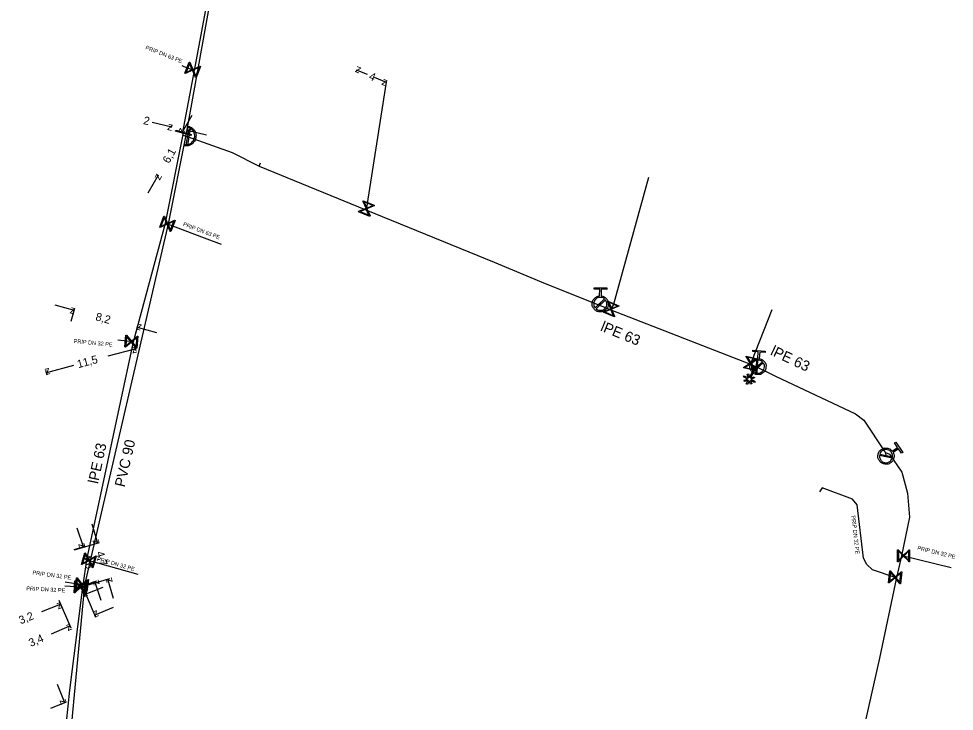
# Model space of a CAD drawing. Extents: x -641905 to -641246, y -1111750 to -1110210.
# Drawn here: x -641704.4 to -641587.5, y -1110847.5 to -1110760.9 of the extents above; entities that cross this region are included whole.
import ezdxf

# ---------------------------------------------------------------- set-up
doc = ezdxf.new("R2010")
doc.units = 0
for name, color, linetype in [('Default', 7, 'Continuous'), ('VP Hydrant', 7, 'Continuous'), ('VP Kótování', 7, 'Continuous'), ('VP Nepropojené křížení', 7, 'Continuous'), ('VP Popis přípojky', 7, 'Continuous'), ('VP Přípojka', 7, 'Continuous'), ('VP Změna materiálu', 7, 'Continuous'), ('VP Řad', 7, 'Continuous'), ('VP Řad - popis', 7, 'Continuous'), ('VP Šoupě', 7, 'Continuous')]:
    doc.layers.add(name, color=color, linetype=linetype)

msp = doc.modelspace()

# ---------------------------------------------------------------- linework, layer by layer
at = {"layer": 'Default'}
for points in [[(-641683.32, -1110774.29), (-641683, -1110774.35), (-641682.73, -1110774.57), (-641682.47, -1110774.79), (-641682.36, -1110775.11), (-641682.26, -1110775.44), (-641682.32, -1110775.75), (-641682.38, -1110776.06), (-641682.59, -1110776.32), (-641682.8, -1110776.59), (-641683.13, -1110776.7), (-641683.45, -1110776.81), (-641683.78, -1110776.75)], [(-641683.75, -1110776.6), (-641683.46, -1110776.65), (-641683.18, -1110776.55), (-641682.89, -1110776.45), (-641682.71, -1110776.22), (-641682.52, -1110775.99), (-641682.47, -1110775.72), (-641682.42, -1110775.45), (-641682.51, -1110775.16), (-641682.6, -1110774.88), (-641682.83, -1110774.69), (-641683.07, -1110774.5), (-641683.35, -1110774.44)], [(-641631.66, -1110795.52), (-641631.3, -1110795.56), (-641631.04, -1110795.82), (-641630.76, -1110796.12), (-641630.76, -1110796.53), (-641630.76, -1110796.95), (-641631.06, -1110797.23), (-641631.36, -1110797.52), (-641631.77, -1110797.52), (-641632.18, -1110797.52), (-641632.47, -1110797.22), (-641632.76, -1110796.93), (-641632.76, -1110796.51), (-641632.76, -1110796.1), (-641632.46, -1110795.81), (-641632.2, -1110795.55), (-641631.84, -1110795.52)], [(-641631.25, -1110795.89), (-641631.46, -1110795.71), (-641631.75, -1110795.71), (-641632.09, -1110795.7), (-641632.33, -1110795.94), (-641632.57, -1110796.17), (-641632.57, -1110796.51), (-641632.58, -1110796.8), (-641632.4, -1110797.02)], [(-641632.27, -1110797.15), (-641632.06, -1110797.33), (-641631.77, -1110797.33), (-641631.43, -1110797.33), (-641631.19, -1110797.1), (-641630.95, -1110796.86), (-641630.95, -1110796.53), (-641630.95, -1110796.24), (-641631.12, -1110796.02)], [(-641611.89, -1110803.37), (-641611.53, -1110803.43), (-641611.29, -1110803.7), (-641611.02, -1110804.02), (-641611.05, -1110804.43), (-641611.08, -1110804.85), (-641611.4, -1110805.12), (-641611.71, -1110805.39), (-641612.12, -1110805.36), (-641612.53, -1110805.33), (-641612.81, -1110805.02), (-641613.08, -1110804.7), (-641613.05, -1110804.29), (-641613.02, -1110803.88), (-641612.71, -1110803.6), (-641612.43, -1110803.36), (-641612.07, -1110803.36)], [(-641611.5, -1110803.76), (-641611.7, -1110803.57), (-641611.99, -1110803.55), (-641612.33, -1110803.52), (-641612.58, -1110803.74), (-641612.84, -1110803.96), (-641612.86, -1110804.3), (-641612.88, -1110804.59), (-641612.72, -1110804.82)], [(-641612.6, -1110804.96), (-641612.4, -1110805.15), (-641612.11, -1110805.17), (-641611.77, -1110805.19), (-641611.52, -1110804.97), (-641611.27, -1110804.75), (-641611.24, -1110804.42), (-641611.22, -1110804.13), (-641611.38, -1110803.9)], [(-641595.17, -1110815.09), (-641595, -1110815.4), (-641595.07, -1110815.76), (-641595.15, -1110816.17), (-641595.5, -1110816.4), (-641595.84, -1110816.63), (-641596.25, -1110816.54), (-641596.65, -1110816.46), (-641596.88, -1110816.12), (-641597.11, -1110815.77), (-641597.03, -1110815.37), (-641596.95, -1110814.96), (-641596.61, -1110814.73), (-641596.26, -1110814.5), (-641595.86, -1110814.58), (-641595.5, -1110814.65), (-641595.27, -1110814.93)], [(-641595.24, -1110815.63), (-641595.21, -1110815.35), (-641595.37, -1110815.11), (-641595.56, -1110814.83), (-641595.89, -1110814.76), (-641596.22, -1110814.7), (-641596.5, -1110814.88), (-641596.75, -1110815.05), (-641596.83, -1110815.32)], [(-641596.86, -1110815.49), (-641596.89, -1110815.77), (-641596.73, -1110816.01), (-641596.54, -1110816.29), (-641596.21, -1110816.36), (-641595.88, -1110816.42), (-641595.6, -1110816.24), (-641595.36, -1110816.08), (-641595.28, -1110815.81)]]:
    msp.add_open_spline(points, degree=3, dxfattribs=at)
at = {"layer": 'VP Hydrant'}
for points in [[(-641631.84, -1110795.52), (-641631.83, -1110794.7), (-641632.52, -1110794.7), (-641632.52, -1110794.51), (-641630.96, -1110794.53), (-641630.96, -1110794.71), (-641631.65, -1110794.7), (-641631.66, -1110795.52)], [(-641632.4, -1110797.02), (-641631.25, -1110795.89)], [(-641631.12, -1110796.02), (-641632.27, -1110797.15)], [(-641612.07, -1110803.36), (-641612.01, -1110802.54), (-641612.7, -1110802.49), (-641612.69, -1110802.31), (-641611.13, -1110802.42), (-641611.14, -1110802.6), (-641611.83, -1110802.55), (-641611.89, -1110803.37)], [(-641612.72, -1110804.82), (-641611.5, -1110803.76)], [(-641611.38, -1110803.9), (-641612.6, -1110804.96)], [(-641595.27, -1110814.93), (-641594.59, -1110814.48), (-641594.97, -1110813.91), (-641594.82, -1110813.8), (-641593.95, -1110815.1), (-641594.11, -1110815.21), (-641594.49, -1110814.63), (-641595.17, -1110815.09)], [(-641595.28, -1110815.81), (-641596.86, -1110815.49)], [(-641596.83, -1110815.32), (-641595.24, -1110815.63)]]:
    msp.add_lwpolyline(points, dxfattribs=at)
at = {"layer": 'VP Kótování'}
for points in [[(-641660.86, -1110767.85), (-641662.23, -1110767.29)], [(-641660.04, -1110768.19), (-641658.52, -1110768.81)], [(-641687.76, -1110773.79), (-641685.33, -1110774.38)], [(-641682.82, -1110772.95), (-641684.04, -1110775.13)], [(-641685.35, -1110774.46), (-641685.27, -1110774.13)], [(-641683.41, -1110774.93), (-641683.33, -1110774.6)], [(-641680.96, -1110775.43), (-641683.39, -1110774.85)], [(-641683.96, -1110775.18), (-641684.26, -1110775.01)], [(-641688.25, -1110782.63), (-641687.02, -1110780.45)], [(-641686.95, -1110780.5), (-641687.24, -1110780.33)], [(-641699.93, -1110796.66), (-641697.52, -1110797.32)], [(-641697.89, -1110798.67), (-641697.45, -1110797.08)], [(-641689.98, -1110800.83), (-641689.54, -1110799.24)], [(-641687.2, -1110800.14), (-641689.61, -1110799.48)], [(-641689.98, -1110801.79), (-641689.82, -1110802.37)], [(-641693.26, -1110803.04), (-641689.89, -1110802.13)], [(-641697.62, -1110804.22), (-641700.99, -1110805.13)], [(-641701.08, -1110804.8), (-641700.92, -1110805.38)], [(-641695.31, -1110824.03), (-641694.61, -1110826.43)], [(-641697.19, -1110824.51), (-641696.4, -1110826.88)], [(-641697.49, -1110827.27), (-641694.37, -1110826.36)], [(-641697.5, -1110827.25), (-641696.16, -1110826.8)], [(-641696.18, -1110831.78), (-641693.06, -1110830.88)], [(-641692.6, -1110833.35), (-641693.3, -1110830.95)], [(-641696.31, -1110832.23), (-641694.83, -1110835.68)], [(-641693.95, -1110831.97), (-641696.27, -1110832.9)], [(-641696.03, -1110831.61), (-641694.69, -1110831.16)], [(-641694.14, -1110833.61), (-641694.93, -1110831.24)], [(-641696.47, -1110832.39), (-641696.18, -1110833.13)], [(-641701.56, -1110835.01), (-641699.24, -1110834.09)], [(-641699.44, -1110833.57), (-641699.15, -1110834.32)], [(-641699.43, -1110833.57), (-641697.95, -1110837.02)], [(-641692.63, -1110834.47), (-641694.93, -1110835.45)], [(-641700.35, -1110837.78), (-641698.05, -1110836.79)], [(-641699.66, -1110844.07), (-641698.72, -1110846.39)], [(-641700.43, -1110847.08), (-641698.49, -1110846.29)]]:
    msp.add_lwpolyline(points, dxfattribs=at)
at = {"layer": 'VP Nepropojené křížení'}
for points in [[(-641683.35, -1110774.44), (-641683.32, -1110774.29)], [(-641683.78, -1110776.75), (-641683.75, -1110776.6)]]:
    msp.add_lwpolyline(points, dxfattribs=at)
at = {"layer": 'VP Přípojka'}
for points in [[(-641684.07, -1110766.71), (-641683.79, -1110766.82), (-641682.47, -1110767.34)], [(-641658.52, -1110768.8), (-641661.01, -1110784.78)], [(-641674.41, -1110779.3), (-641674.24, -1110778.87)], [(-641630.1, -1110796.69), (-641625.69, -1110780.66)], [(-641686.1, -1110786.43), (-641681.27, -1110788.25), (-641679.15, -1110789.05)], [(-641631.84, -1110796.67), (-641631.76, -1110796.52), (-641631.68, -1110796.26)], [(-641630.43, -1110797.27), (-641630.4, -1110797.16), (-641630.1, -1110796.69)], [(-641612.98, -1110804.08), (-641612.95, -1110803.95), (-641612.83, -1110803.7), (-641610.26, -1110797.21)], [(-641690.12, -1110801.26), (-641692.07, -1110801.07)], [(-641612.05, -1110804.36), (-641612.19, -1110804.35), (-641612.33, -1110804.34)], [(-641596.13, -1110815.11), (-641596.05, -1110815.56)], [(-641594.72, -1110830.74), (-641594.9, -1110830.72), (-641597.74, -1110829.79), (-641598.43, -1110829.13), (-641598.86, -1110828.32), (-641599.64, -1110821.66), (-641600.23, -1110820.96), (-641604.04, -1110819.53), (-641604.34, -1110820.01)], [(-641695.92, -1110828.52), (-641689.56, -1110830.34)], [(-641594.13, -1110828.01), (-641593.84, -1110828.01), (-641587.9, -1110829.48)], [(-641696.45, -1110831.95), (-641696.73, -1110831.94), (-641698.7, -1110831.83)], [(-641696.41, -1110831.68), (-641696.56, -1110831.64), (-641698.63, -1110831.32)]]:
    msp.add_lwpolyline(points, dxfattribs=at)
at = {"layer": 'VP Změna materiálu'}
msp.add_lwpolyline([(-641613.13, -1110806.13), (-641613.37, -1110806.61), (-641613.51, -1110806.54), (-641613.28, -1110806.07), (-641613.72, -1110806.22), (-641613.77, -1110806.07), (-641613.33, -1110805.92), (-641613.84, -1110805.66), (-641613.77, -1110805.52), (-641613.25, -1110805.78), (-641613.4, -1110805.33), (-641613.25, -1110805.28), (-641613.11, -1110805.72), (-641612.4, -1110804.3), (-641612.26, -1110804.37), (-641612.97, -1110805.8), (-641612.52, -1110805.65), (-641612.47, -1110805.79), (-641612.92, -1110805.95), (-641612.4, -1110806.21), (-641612.47, -1110806.35), (-641612.98, -1110806.09), (-641612.83, -1110806.53), (-641612.98, -1110806.58), (-641613.13, -1110806.13)], dxfattribs=at)
at = {"layer": 'VP Řad'}
for points in [[(-641677.16, -1110922.63), (-641678.03, -1110920.93), (-641690.55, -1110919.49), (-641702.17, -1110918.14), (-641702.78, -1110917.85), (-641702.94, -1110917.33), (-641701.3, -1110896.82), (-641699.93, -1110871.85), (-641699.85, -1110870.64), (-641696.18, -1110831.68), (-641685.71, -1110786.51), (-641683.53, -1110775.42), (-641678.5, -1110747.68)], [(-641698.05, -1110844.81), (-641696.45, -1110831.95), (-641696.41, -1110831.68), (-641695.92, -1110828.52), (-641690.12, -1110801.26), (-641686.1, -1110786.43), (-641683.86, -1110775.15), (-641683.88, -1110774.79), (-641683.8, -1110774.38), (-641682.47, -1110767.34), (-641678.79, -1110747.62)], [(-641683.91, -1110775.42), (-641683.25, -1110775.65), (-641677.78, -1110777.59), (-641674.41, -1110779.3), (-641661.06, -1110784.76), (-641645.03, -1110791.3), (-641638.64, -1110793.98), (-641631.84, -1110796.67), (-641630.43, -1110797.27), (-641612.98, -1110804.08), (-641612.33, -1110804.34)], [(-641612.33, -1110804.34), (-641609.85, -1110805.57), (-641599.86, -1110810.26), (-641598.82, -1110811.05), (-641596.18, -1110815.02), (-641596.13, -1110815.11), (-641595.92, -1110815.19), (-641595.62, -1110815.3), (-641594.06, -1110817.56), (-641593.35, -1110820.19), (-641593.11, -1110823.18), (-641594.13, -1110828.01), (-641594.72, -1110830.74), (-641596.88, -1110840.82), (-641599.59, -1110853.03)], [(-641677.56, -1110922.6), (-641677.62, -1110922.5), (-641678.46, -1110921.27), (-641702.22, -1110918.54), (-641703.16, -1110917.97), (-641703.32, -1110917.44), (-641701.7, -1110896.8), (-641701.54, -1110894.08), (-641700.29, -1110871.19), (-641700.48, -1110868.17), (-641698.9, -1110852.81), (-641698.05, -1110844.81)]]:
    msp.add_lwpolyline(points, dxfattribs=at)
at = {"layer": 'VP Šoupě'}
for points in [[(-641681.73, -1110766.83), (-641682.28, -1110768.23), (-641682.34, -1110768.2), (-641682.39, -1110768.08), (-641682.72, -1110767.31), (-641683.61, -1110767.7), (-641683.67, -1110767.68), (-641683.13, -1110766.28), (-641683.06, -1110766.3), (-641682.68, -1110767.2), (-641681.91, -1110766.86), (-641681.79, -1110766.81), (-641681.73, -1110766.83)], [(-641683.53, -1110767.57), (-641682.76, -1110767.23), (-641683.1, -1110766.46), (-641683.53, -1110767.57)], [(-641681.87, -1110766.94), (-641682.64, -1110767.28), (-641682.31, -1110768.04), (-641681.87, -1110766.94)], [(-641682.91, -1110775.48), (-641684.84, -1110774.94), (-641684.81, -1110774.82), (-641682.88, -1110775.36), (-641682.91, -1110775.48)], [(-641683.01, -1110774.68), (-641683.37, -1110776.65), (-641683.5, -1110776.62), (-641683.13, -1110774.66), (-641683.01, -1110774.68)], [(-641661.39, -1110783.62), (-641660, -1110784.19), (-641660.03, -1110784.25), (-641660.15, -1110784.3), (-641660.92, -1110784.62), (-641660.54, -1110785.52), (-641660.57, -1110785.58), (-641661.96, -1110785.01), (-641661.93, -1110784.95), (-641661.04, -1110784.57), (-641661.36, -1110783.8), (-641661.42, -1110783.68), (-641661.39, -1110783.62)], [(-641661.28, -1110783.77), (-641660.96, -1110784.54), (-641660.18, -1110784.22), (-641661.28, -1110783.77)], [(-641660.67, -1110785.43), (-641661, -1110784.66), (-641661.78, -1110784.98), (-641660.67, -1110785.43)], [(-641684.9, -1110786.08), (-641685.43, -1110787.48), (-641685.49, -1110787.46), (-641685.54, -1110787.34), (-641685.89, -1110786.57), (-641686.77, -1110786.98), (-641686.83, -1110786.95), (-641686.3, -1110785.55), (-641686.24, -1110785.57), (-641685.84, -1110786.46), (-641685.08, -1110786.11), (-641684.96, -1110786.05), (-641684.9, -1110786.08)], [(-641686.69, -1110786.84), (-641685.92, -1110786.49), (-641686.27, -1110785.73), (-641686.69, -1110786.84)], [(-641685.04, -1110786.19), (-641685.81, -1110786.54), (-641685.46, -1110787.3), (-641685.04, -1110786.19)], [(-641630.8, -1110796.18), (-641629.42, -1110796.76), (-641629.44, -1110796.82), (-641629.56, -1110796.87), (-641630.34, -1110797.18), (-641629.98, -1110798.08), (-641630, -1110798.14), (-641631.38, -1110797.56), (-641631.36, -1110797.5), (-641630.46, -1110797.13), (-641630.77, -1110796.36), (-641630.82, -1110796.24), (-641630.8, -1110796.18)], [(-641630.69, -1110796.32), (-641630.37, -1110797.1), (-641629.6, -1110796.79), (-641630.69, -1110796.32)], [(-641630.11, -1110798), (-641630.42, -1110797.22), (-641631.2, -1110797.53), (-641630.11, -1110798)], [(-641689.55, -1110800.57), (-641689.69, -1110802.06), (-641689.76, -1110802.05), (-641689.84, -1110801.95), (-641690.37, -1110801.3), (-641691.12, -1110801.92), (-641691.18, -1110801.91), (-641691.04, -1110800.42), (-641690.97, -1110800.43), (-641690.36, -1110801.18), (-641689.71, -1110800.64), (-641689.61, -1110800.56), (-641689.55, -1110800.57)], [(-641691.08, -1110801.77), (-641690.43, -1110801.23), (-641690.96, -1110800.59), (-641691.08, -1110801.77)], [(-641689.65, -1110800.71), (-641690.3, -1110801.25), (-641689.77, -1110801.89), (-641689.65, -1110800.71)], [(-641613.51, -1110803.05), (-641612.05, -1110803.39), (-641612.07, -1110803.45), (-641612.18, -1110803.52), (-641612.89, -1110803.96), (-641612.37, -1110804.78), (-641612.39, -1110804.85), (-641613.85, -1110804.51), (-641613.83, -1110804.45), (-641613.01, -1110803.93), (-641613.46, -1110803.22), (-641613.53, -1110803.11), (-641613.51, -1110803.05)], [(-641612.52, -1110804.72), (-641612.96, -1110804.01), (-641613.68, -1110804.46), (-641612.52, -1110804.72)], [(-641613.38, -1110803.18), (-641612.94, -1110803.89), (-641612.23, -1110803.44), (-641613.38, -1110803.18)], [(-641612.09, -1110803.6), (-641612.2, -1110805.1), (-641612.29, -1110805.09), (-641612.18, -1110803.6), (-641612.09, -1110803.6)], [(-641593.09, -1110827.26), (-641593.09, -1110828.76), (-641593.15, -1110828.76), (-641593.24, -1110828.67), (-641593.84, -1110828.07), (-641594.52, -1110828.76), (-641594.59, -1110828.76), (-641594.59, -1110827.26), (-641594.52, -1110827.26), (-641593.84, -1110827.95), (-641593.24, -1110827.35), (-641593.15, -1110827.26), (-641593.09, -1110827.26)], [(-641594.49, -1110828.61), (-641593.9, -1110828.01), (-641594.49, -1110827.42), (-641594.49, -1110828.61)], [(-641593.18, -1110827.42), (-641593.77, -1110828.01), (-641593.18, -1110828.6), (-641593.18, -1110827.42)], [(-641694.75, -1110828.07), (-641695.17, -1110829.51), (-641695.23, -1110829.49), (-641695.29, -1110829.38), (-641695.7, -1110828.65), (-641696.54, -1110829.12), (-641696.61, -1110829.1), (-641696.2, -1110827.66), (-641696.13, -1110827.68), (-641695.66, -1110828.53), (-641694.93, -1110828.12), (-641694.82, -1110828.05), (-641694.75, -1110828.07)], [(-641696.48, -1110828.98), (-641695.74, -1110828.57), (-641696.15, -1110827.83), (-641696.48, -1110828.98)], [(-641694.89, -1110828.2), (-641695.62, -1110828.6), (-641695.21, -1110829.33), (-641694.89, -1110828.2)], [(-641594.08, -1110830.05), (-641594.23, -1110831.54), (-641594.29, -1110831.53), (-641594.37, -1110831.43), (-641594.9, -1110830.78), (-641595.65, -1110831.4), (-641595.72, -1110831.39), (-641595.57, -1110829.9), (-641595.51, -1110829.91), (-641594.89, -1110830.66), (-641594.24, -1110830.13), (-641594.15, -1110830.04), (-641594.08, -1110830.05)], [(-641695.72, -1110830.99), (-641695.92, -1110832.48), (-641695.99, -1110832.47), (-641696.06, -1110832.37), (-641696.57, -1110831.7), (-641697.34, -1110832.29), (-641697.41, -1110832.28), (-641697.21, -1110830.79), (-641697.14, -1110830.8), (-641696.55, -1110831.58), (-641695.89, -1110831.07), (-641695.78, -1110830.99), (-641695.72, -1110830.99)], [(-641697.29, -1110832.14), (-641696.62, -1110831.63), (-641697.13, -1110830.96), (-641697.29, -1110832.14)], [(-641595.61, -1110831.25), (-641594.96, -1110830.71), (-641595.5, -1110830.07), (-641595.61, -1110831.25)], [(-641594.19, -1110830.19), (-641594.84, -1110830.73), (-641594.31, -1110831.37), (-641594.19, -1110830.19)], [(-641695.94, -1110831.23), (-641696.02, -1110832.73), (-641696.09, -1110832.72), (-641696.17, -1110832.62), (-641696.73, -1110832), (-641697.45, -1110832.65), (-641697.52, -1110832.65), (-641697.44, -1110831.15), (-641697.37, -1110831.15), (-641696.72, -1110831.88), (-641696.1, -1110831.31), (-641696.01, -1110831.23), (-641695.94, -1110831.23)], [(-641697.42, -1110832.5), (-641696.79, -1110831.93), (-641697.35, -1110831.31), (-641697.42, -1110832.5)], [(-641696.04, -1110831.38), (-641696.67, -1110831.94), (-641696.11, -1110832.56), (-641696.04, -1110831.38)], [(-641695.83, -1110831.14), (-641696.5, -1110831.65), (-641695.99, -1110832.31), (-641695.83, -1110831.14)]]:
    msp.add_lwpolyline(points, dxfattribs=at)

# ---------------------------------------------------------------- texts
at = {"layer": 'VP Kótování'}
for s, rotation, p in [('z', 157.7811, (-641661.58, -1110767.02)), ('4', 337.7811, (-641660.77, -1110768.43)), ('z', 337.7811, (-641659.18, -1110769.08)), ('2', 346.4167, (-641688.94, -1110774.02)), ('z', 346.4167, (-641685.94, -1110774.75)), ('z', 240.7126, (-641684.23, -1110774.45)), ('z', 166.4167, (-641682.78, -1110774.48)), ('6,1', 60.7126, (-641685.66, -1110779.04)), ('z', 60.7126, (-641686.83, -1110781.13)), ('z', 344.7099, (-641698.13, -1110797.67)), ('8,2', 344.7099, (-641694.92, -1110798.55)), ('z', 164.7099, (-641689, -1110799.13)), ('z', 15.1609, (-641690.24, -1110802.74)), ('11,5', 15.1609, (-641697, -1110804.57)), ('z', 195.1609, (-641700.64, -1110804.52)), ('z', 288.571, (-641697.03, -1110826.57)), ('z', 286.2068, (-641695.23, -1110826.09)), ('4,7', 286.2068, (-641694.79, -1110827.61)), ('4,6', 288.571, (-641696.55, -1110828)), ('z', 108.571, (-641694.3, -1110831.56)), ('z', 106.2068, (-641692.68, -1110831.29)), ('z', 201.7691, (-641695.99, -1110832.25)), ('z', 21.7691, (-641699.52, -1110834.74)), ('3,2', 21.7691, (-641704.2, -1110836.6)), ('z', 203.2022, (-641694.66, -1110834.8)), ('z', 23.2022, (-641698.31, -1110837.45)), ('3,4', 23.2022, (-641702.94, -1110839.43)), ('z', 292.149, (-641699.37, -1110846.11))]:
    msp.add_text(s, height=1, rotation=rotation, dxfattribs=at).set_placement(p)
at = {"layer": 'VP Popis přípojky'}
for s, rotation, p in [('PRIP DN 63 PE', 338.5523, (-641688.65, -1110764.66)), ('PRIP DN 63 PE', 339.353, (-641683.96, -1110786.75)), ('PRIP DN 32 PE', 354.4349, (-641697.59, -1110801.41)), ('PRIP DN 32 PE', 276.6799, (-641600.39, -1110823.01)), ('PRIP DN 32 PE', 346.0957, (-641592.17, -1110827.25)), ('PRIP DN 32 PE', 344.0308, (-641694.71, -1110828.61)), ('PRIP DN 32 PE', 352.2597, (-641702.75, -1110830.35)), ('PRIP DN 32 PE', 356.8983, (-641703.51, -1110832.34))]:
    msp.add_text(s, height=0.5, rotation=rotation, dxfattribs=at).set_placement(p)
at = {"layer": 'VP Řad - popis'}
for s, rotation, p in [('lPE 63', 337.8053, (-641631.83, -1110799.84)), ('lPE 63', 334.8514, (-641610.59, -1110802.85)), ('PVC 90', 76.9498, (-641691.21, -1110819.51)), ('lPE 63', 77.9885, (-641694.53, -1110819.09))]:
    msp.add_text(s, height=1.3, rotation=rotation, dxfattribs=at).set_placement(p)

doc.saveas('drawing.dxf')
